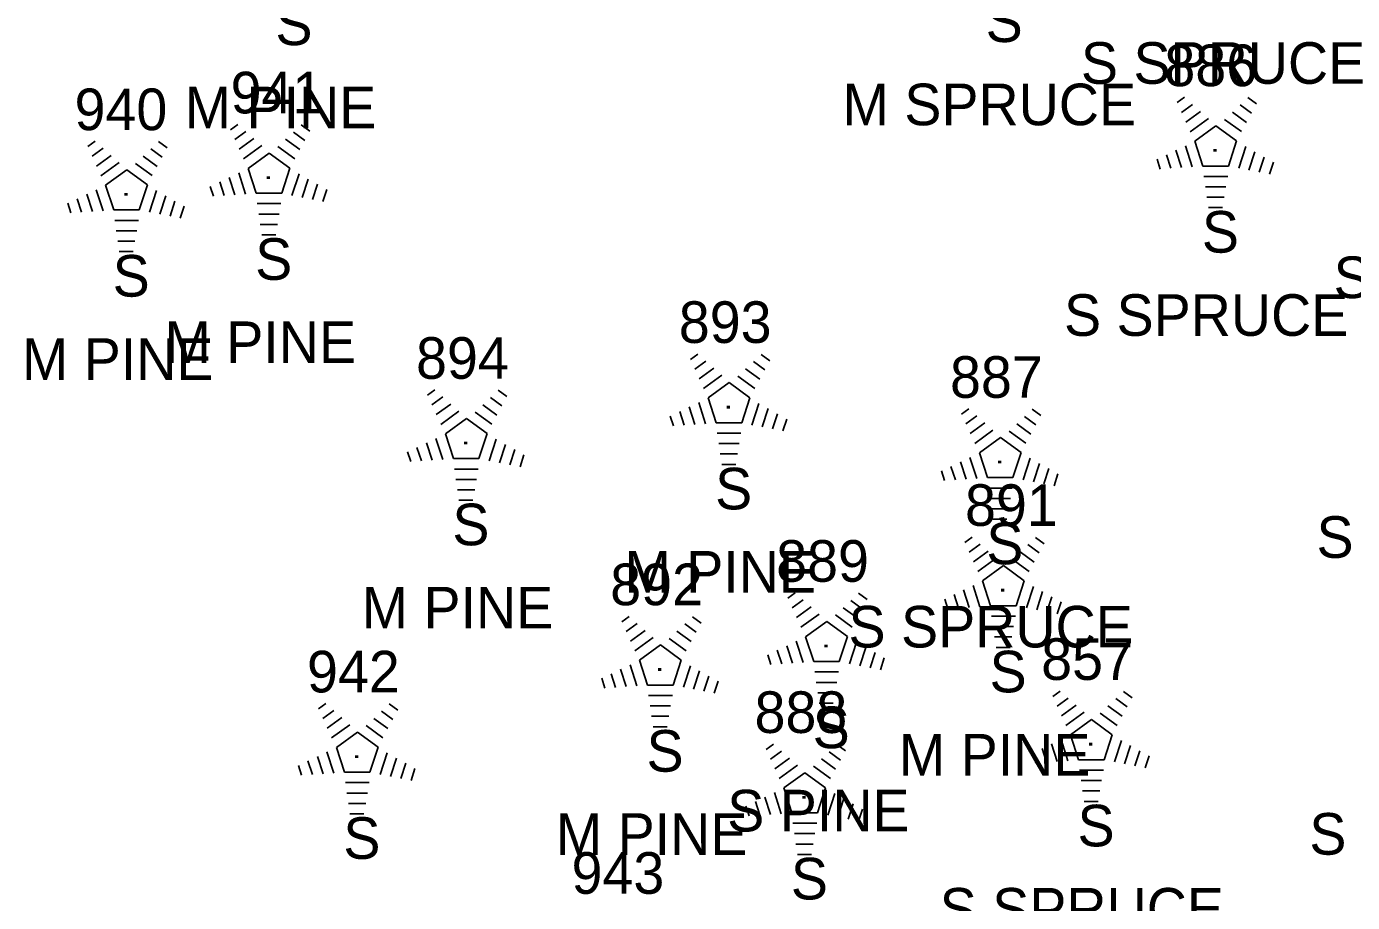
# Model space of a CAD drawing. Extents: x 1545627 to 1546562, y 571176 to 576667.
# Drawn here: x 1546147.4 to 1546211.1, y 572351.6 to 572393.7 of the extents above; entities that cross this region are included whole.
import ezdxf

# ---------------------------------------------------------------- set-up
doc = ezdxf.new("R2010")
doc.units = 0
for name, color, linetype in [('L_A', 7, 'Continuous'), ('L_C', 7, 'Continuous'), ('L_I', 7, 'Continuous'), ('LTC', 7, 'Continuous')]:
    doc.layers.add(name, color=color, linetype=linetype)

msp = doc.modelspace()

# ---------------------------------------------------------------- linework, layer by layer
at = {"layer": 'LTC'}
for p, q in [((1546202.707, 572390.014), (1546203.061, 572390.271)), ((1546206.105, 572390.254), (1546206.524, 572389.95)), ((1546202.916, 572389.548), (1546203.445, 572389.933)), ((1546203.126, 572389.083), (1546203.83, 572389.594)), ((1546205.363, 572389.558), (1546206.042, 572389.064)), ((1546205.734, 572389.906), (1546206.283, 572389.507)), ((1546157.171, 572388.707), (1546157.526, 572388.965)), ((1546160.57, 572388.948), (1546160.989, 572388.643)), ((1546203.335, 572388.617), (1546204.214, 572389.255)), ((1546203.56, 572388.162), (1546204.572, 572388.896)), ((1546204.572, 572388.896), (1546205.569, 572388.171)), ((1546204.992, 572389.209), (1546205.801, 572388.62)), ((1546150.316, 572387.9), (1546150.67, 572388.158)), ((1546153.714, 572388.141), (1546154.133, 572387.836)), ((1546157.381, 572388.242), (1546157.91, 572388.626)), ((1546157.59, 572387.776), (1546158.294, 572388.287)), ((1546159.827, 572388.251), (1546160.507, 572387.757)), ((1546160.198, 572388.6), (1546160.748, 572388.2)), ((1546203.56, 572388.162), (1546203.947, 572386.968)), ((1546205.569, 572388.171), (1546205.178, 572386.968)), ((1546150.525, 572387.435), (1546151.055, 572387.819)), ((1546150.735, 572386.969), (1546151.439, 572387.48)), ((1546153.343, 572387.792), (1546153.893, 572387.393)), ((1546157.8, 572387.31), (1546158.678, 572387.948)), ((1546158.025, 572386.855), (1546159.036, 572387.59)), ((1546159.036, 572387.59), (1546160.033, 572386.865)), ((1546159.456, 572387.903), (1546160.266, 572387.314)), ((1546202.195, 572387.51), (1546202.406, 572386.858)), ((1546202.65, 572387.726), (1546202.921, 572386.891)), ((1546203.105, 572387.943), (1546203.436, 572386.923)), ((1546206.006, 572387.9), (1546205.668, 572386.861)), ((1546206.451, 572387.65), (1546206.163, 572386.765)), ((1546150.945, 572386.503), (1546151.823, 572387.141)), ((1546152.601, 572387.096), (1546153.41, 572386.507)), ((1546152.972, 572387.444), (1546153.651, 572386.95)), ((1546158.025, 572386.855), (1546158.412, 572385.662)), ((1546160.033, 572386.865), (1546159.642, 572385.662)), ((1546201.739, 572387.293), (1546201.891, 572386.825)), ((1546205.178, 572386.968), (1546203.947, 572386.968)), ((1546206.895, 572387.4), (1546206.658, 572386.67)), ((1546207.34, 572387.15), (1546207.153, 572386.575)), ((1546151.169, 572386.048), (1546152.181, 572386.783)), ((1546152.181, 572386.783), (1546153.178, 572386.058)), ((1546156.659, 572386.203), (1546156.871, 572385.552)), ((1546157.115, 572386.42), (1546157.386, 572385.585)), ((1546157.57, 572386.636), (1546157.901, 572385.617)), ((1546160.471, 572386.594), (1546160.133, 572385.555)), ((1546160.915, 572386.344), (1546160.628, 572385.459)), ((1546205.139, 572386.468), (1546203.995, 572386.468)), ((1546150.259, 572385.613), (1546150.53, 572384.777)), ((1546150.715, 572385.829), (1546151.045, 572384.81)), ((1546151.169, 572386.048), (1546151.556, 572384.855)), ((1546153.178, 572386.058), (1546152.787, 572384.855)), ((1546153.615, 572385.787), (1546153.278, 572384.747)), ((1546156.204, 572385.987), (1546156.356, 572385.519)), ((1546159.642, 572385.662), (1546158.412, 572385.662)), ((1546161.36, 572386.094), (1546161.123, 572385.364)), ((1546161.804, 572385.843), (1546161.617, 572385.269)), ((1546205.055, 572385.968), (1546204.067, 572385.968)), ((1546149.348, 572385.179), (1546149.5, 572384.711)), ((1546149.804, 572385.396), (1546150.015, 572384.744)), ((1546154.06, 572385.536), (1546153.773, 572384.652)), ((1546154.505, 572385.286), (1546154.268, 572384.557)), ((1546154.949, 572385.036), (1546154.762, 572384.462)), ((1546159.604, 572385.162), (1546158.459, 572385.162)), ((1546204.972, 572385.468), (1546204.14, 572385.468)), ((1546204.888, 572384.968), (1546204.213, 572384.968)), ((1546152.787, 572384.855), (1546151.556, 572384.855)), ((1546152.748, 572384.355), (1546151.604, 572384.355)), ((1546159.52, 572384.662), (1546158.532, 572384.662)), ((1546152.665, 572383.855), (1546151.676, 572383.855)), ((1546159.436, 572384.162), (1546158.605, 572384.162)), ((1546159.352, 572383.662), (1546158.677, 572383.662)), ((1546152.581, 572383.355), (1546151.749, 572383.355)), ((1546152.497, 572382.855), (1546151.822, 572382.855)), ((1546179.296, 572377.674), (1546179.65, 572377.932)), ((1546182.694, 572377.914), (1546183.113, 572377.61)), ((1546179.505, 572377.209), (1546180.034, 572377.593)), ((1546182.323, 572377.566), (1546182.872, 572377.167)), ((1546179.715, 572376.743), (1546180.419, 572377.254)), ((1546179.924, 572376.277), (1546180.803, 572376.915)), ((1546181.581, 572376.869), (1546182.39, 572376.281)), ((1546181.952, 572377.218), (1546182.631, 572376.724)), ((1546166.656, 572375.95), (1546167.011, 572376.208)), ((1546170.054, 572376.191), (1546170.474, 572375.886)), ((1546180.149, 572375.822), (1546181.161, 572376.557)), ((1546181.161, 572376.557), (1546182.158, 572375.832)), ((1546166.866, 572375.485), (1546167.395, 572375.869)), ((1546167.075, 572375.019), (1546167.779, 572375.53)), ((1546169.312, 572375.494), (1546169.992, 572375)), ((1546169.683, 572375.842), (1546170.233, 572375.443)), ((1546179.239, 572375.387), (1546179.51, 572374.551)), ((1546179.694, 572375.603), (1546180.025, 572374.584)), ((1546180.149, 572375.822), (1546180.536, 572374.629)), ((1546182.158, 572375.832), (1546181.766, 572374.629)), ((1546182.595, 572375.561), (1546182.257, 572374.521)), ((1546167.285, 572374.553), (1546168.163, 572375.191)), ((1546167.509, 572374.098), (1546168.521, 572374.833)), ((1546168.521, 572374.833), (1546169.518, 572374.108)), ((1546168.941, 572375.146), (1546169.751, 572374.557)), ((1546178.328, 572374.953), (1546178.48, 572374.485)), ((1546178.784, 572375.17), (1546178.995, 572374.518)), ((1546183.04, 572375.31), (1546182.752, 572374.426)), ((1546183.484, 572375.06), (1546183.247, 572374.331)), ((1546183.929, 572374.81), (1546183.742, 572374.236)), ((1546192.34, 572375.038), (1546192.695, 572375.295)), ((1546192.55, 572374.572), (1546193.079, 572374.956)), ((1546195.367, 572374.93), (1546195.917, 572374.53)), ((1546195.739, 572375.278), (1546196.158, 572374.973)), ((1546167.509, 572374.098), (1546167.897, 572372.905)), ((1546169.518, 572374.108), (1546169.127, 572372.905)), ((1546181.766, 572374.629), (1546180.536, 572374.629)), ((1546181.728, 572374.129), (1546180.584, 572374.129)), ((1546192.76, 572374.106), (1546193.463, 572374.618)), ((1546192.969, 572373.64), (1546193.847, 572374.278)), ((1546194.625, 572374.233), (1546195.435, 572373.644)), ((1546194.997, 572374.581), (1546195.676, 572374.088)), ((1546166.144, 572373.446), (1546166.356, 572372.795)), ((1546166.599, 572373.663), (1546166.871, 572372.827)), ((1546167.055, 572373.879), (1546167.386, 572372.86)), ((1546169.956, 572373.837), (1546169.618, 572372.797)), ((1546170.4, 572373.587), (1546170.113, 572372.702)), ((1546181.644, 572373.629), (1546180.656, 572373.629)), ((1546193.194, 572373.185), (1546194.205, 572373.92)), ((1546194.205, 572373.92), (1546195.202, 572373.195)), ((1546165.689, 572373.23), (1546165.841, 572372.762)), ((1546169.127, 572372.905), (1546167.897, 572372.905)), ((1546170.845, 572373.337), (1546170.608, 572372.607)), ((1546171.289, 572373.086), (1546171.102, 572372.512)), ((1546181.561, 572373.129), (1546180.729, 572373.129)), ((1546192.739, 572372.966), (1546193.07, 572371.947)), ((1546193.194, 572373.185), (1546193.581, 572371.992)), ((1546195.202, 572373.195), (1546194.811, 572371.992)), ((1546195.64, 572372.924), (1546195.302, 572371.885)), ((1546169.089, 572372.405), (1546167.944, 572372.405)), ((1546181.477, 572372.629), (1546180.802, 572372.629)), ((1546191.373, 572372.317), (1546191.525, 572371.849)), ((1546191.828, 572372.533), (1546192.04, 572371.882)), ((1546192.284, 572372.75), (1546192.555, 572371.915)), ((1546196.085, 572372.674), (1546195.797, 572371.789)), ((1546196.529, 572372.424), (1546196.292, 572371.694)), ((1546196.973, 572372.173), (1546196.787, 572371.599)), ((1546169.005, 572371.905), (1546168.017, 572371.905)), ((1546194.811, 572371.992), (1546193.581, 572371.992)), ((1546168.921, 572371.405), (1546168.089, 572371.405)), ((1546168.837, 572370.905), (1546168.162, 572370.905)), ((1546194.773, 572371.492), (1546193.628, 572371.492)), ((1546194.689, 572370.992), (1546193.701, 572370.992)), ((1546194.605, 572370.492), (1546193.774, 572370.492)), ((1546194.522, 572369.992), (1546193.847, 572369.992)), ((1546192.494, 572368.88), (1546192.849, 572369.138)), ((1546195.892, 572369.12), (1546196.312, 572368.816)), ((1546192.704, 572368.415), (1546193.233, 572368.799)), ((1546192.913, 572367.949), (1546193.617, 572368.46)), ((1546195.15, 572368.424), (1546195.829, 572367.93)), ((1546195.521, 572368.772), (1546196.071, 572368.373)), ((1546193.123, 572367.483), (1546194.001, 572368.121)), ((1546193.347, 572367.028), (1546194.359, 572367.763)), ((1546194.359, 572367.763), (1546195.356, 572367.038)), ((1546194.779, 572368.075), (1546195.589, 572367.487)), ((1546183.987, 572366.196), (1546184.341, 572366.454)), ((1546187.385, 572366.437), (1546187.804, 572366.132)), ((1546192.437, 572366.593), (1546192.709, 572365.757)), ((1546192.893, 572366.809), (1546193.224, 572365.79)), ((1546193.347, 572367.028), (1546193.734, 572365.835)), ((1546195.356, 572367.038), (1546194.965, 572365.835)), ((1546195.794, 572366.767), (1546195.456, 572365.727)), ((1546196.238, 572366.516), (1546195.951, 572365.632)), ((1546184.196, 572365.731), (1546184.725, 572366.115)), ((1546187.014, 572366.088), (1546187.563, 572365.689)), ((1546191.527, 572366.159), (1546191.679, 572365.691)), ((1546191.982, 572366.376), (1546192.194, 572365.724)), ((1546194.965, 572365.835), (1546193.734, 572365.835)), ((1546196.683, 572366.266), (1546196.446, 572365.537)), ((1546197.127, 572366.016), (1546196.94, 572365.442)), ((1546175.995, 572365.069), (1546176.35, 572365.326)), ((1546179.393, 572365.309), (1546179.813, 572365.004)), ((1546184.406, 572365.265), (1546185.11, 572365.776)), ((1546184.615, 572364.799), (1546185.494, 572365.437)), ((1546186.272, 572365.392), (1546187.081, 572364.803)), ((1546186.643, 572365.74), (1546187.322, 572365.246)), ((1546194.927, 572365.335), (1546193.782, 572365.335)), ((1546176.205, 572364.603), (1546176.734, 572364.987)), ((1546176.414, 572364.137), (1546177.118, 572364.649)), ((1546178.651, 572364.612), (1546179.331, 572364.119)), ((1546179.022, 572364.961), (1546179.572, 572364.562)), ((1546184.84, 572364.344), (1546185.852, 572365.079)), ((1546185.852, 572365.079), (1546186.849, 572364.354)), ((1546194.843, 572364.835), (1546193.854, 572364.835)), ((1546176.624, 572363.672), (1546177.502, 572364.309)), ((1546176.848, 572363.217), (1546177.86, 572363.951)), ((1546177.86, 572363.951), (1546178.857, 572363.226)), ((1546178.28, 572364.264), (1546179.09, 572363.675)), ((1546183.93, 572363.909), (1546184.201, 572363.073)), ((1546184.385, 572364.125), (1546184.716, 572363.106)), ((1546184.84, 572364.344), (1546185.227, 572363.151)), ((1546186.849, 572364.354), (1546186.458, 572363.151)), ((1546187.286, 572364.083), (1546186.948, 572363.043)), ((1546194.759, 572364.335), (1546193.927, 572364.335)), ((1546183.019, 572363.476), (1546183.171, 572363.008)), ((1546183.475, 572363.692), (1546183.686, 572363.041)), ((1546187.731, 572363.833), (1546187.443, 572362.948)), ((1546188.175, 572363.583), (1546187.938, 572362.853)), ((1546188.62, 572363.332), (1546188.433, 572362.758)), ((1546194.675, 572363.835), (1546194, 572363.835)), ((1546175.938, 572362.781), (1546176.21, 572361.946)), ((1546176.394, 572362.997), (1546176.725, 572361.978)), ((1546176.848, 572363.217), (1546177.236, 572362.023)), ((1546178.857, 572363.226), (1546178.466, 572362.023)), ((1546179.295, 572362.955), (1546178.957, 572361.916)), ((1546179.739, 572362.705), (1546179.452, 572361.82)), ((1546186.458, 572363.151), (1546185.227, 572363.151)), ((1546186.419, 572362.651), (1546185.275, 572362.651)), ((1546175.028, 572362.348), (1546175.18, 572361.88)), ((1546175.483, 572362.564), (1546175.695, 572361.913)), ((1546178.466, 572362.023), (1546177.236, 572362.023)), ((1546180.184, 572362.455), (1546179.947, 572361.725)), ((1546180.628, 572362.204), (1546180.441, 572361.63)), ((1546186.335, 572362.151), (1546185.347, 572362.151)), ((1546178.428, 572361.523), (1546177.283, 572361.523)), ((1546186.252, 572361.651), (1546185.42, 572361.651)), ((1546196.725, 572361.478), (1546197.08, 572361.736)), ((1546196.935, 572361.013), (1546197.464, 572361.397)), ((1546199.752, 572361.371), (1546200.302, 572360.971)), ((1546200.124, 572361.719), (1546200.543, 572361.414)), ((1546161.413, 572360.878), (1546161.767, 572361.136)), ((1546161.622, 572360.413), (1546162.151, 572360.797)), ((1546164.44, 572360.77), (1546164.989, 572360.371)), ((1546164.811, 572361.119), (1546165.23, 572360.814)), ((1546178.344, 572361.023), (1546177.356, 572361.023)), ((1546186.168, 572361.151), (1546185.493, 572361.151)), ((1546197.144, 572360.547), (1546197.848, 572361.058)), ((1546197.354, 572360.081), (1546198.232, 572360.719)), ((1546199.381, 572361.022), (1546200.061, 572360.528)), ((1546161.832, 572359.947), (1546162.536, 572360.458)), ((1546162.041, 572359.481), (1546162.92, 572360.119)), ((1546163.698, 572360.074), (1546164.507, 572359.485)), ((1546164.069, 572360.422), (1546164.748, 572359.928)), ((1546178.26, 572360.523), (1546177.428, 572360.523)), ((1546197.579, 572359.626), (1546198.59, 572360.361)), ((1546198.59, 572360.361), (1546199.587, 572359.636)), ((1546199.01, 572360.674), (1546199.82, 572360.085)), ((1546162.266, 572359.026), (1546163.278, 572359.761)), ((1546163.278, 572359.761), (1546164.275, 572359.036)), ((1546178.176, 572360.023), (1546177.501, 572360.023)), ((1546197.579, 572359.626), (1546197.966, 572358.433)), ((1546199.587, 572359.636), (1546199.196, 572358.433)), ((1546161.811, 572358.807), (1546162.142, 572357.788)), ((1546162.266, 572359.026), (1546162.653, 572357.833)), ((1546164.275, 572359.036), (1546163.883, 572357.833)), ((1546182.937, 572358.928), (1546183.292, 572359.185)), ((1546183.147, 572358.462), (1546183.676, 572358.847)), ((1546185.965, 572358.82), (1546186.514, 572358.421)), ((1546186.336, 572359.168), (1546186.755, 572358.864)), ((1546196.213, 572358.974), (1546196.425, 572358.323)), ((1546196.669, 572359.191), (1546196.94, 572358.356)), ((1546197.124, 572359.407), (1546197.455, 572358.388)), ((1546200.025, 572359.365), (1546199.687, 572358.326)), ((1546200.469, 572359.115), (1546200.182, 572358.23)), ((1546200.914, 572358.865), (1546200.677, 572358.135)), ((1546160.445, 572358.157), (1546160.597, 572357.69)), ((1546160.901, 572358.374), (1546161.112, 572357.722)), ((1546161.356, 572358.591), (1546161.627, 572357.755)), ((1546164.712, 572358.765), (1546164.374, 572357.725)), ((1546165.157, 572358.515), (1546164.869, 572357.63)), ((1546165.601, 572358.265), (1546165.364, 572357.535)), ((1546183.357, 572357.997), (1546184.06, 572358.508)), ((1546183.566, 572357.531), (1546184.445, 572358.169)), ((1546185.594, 572358.472), (1546186.273, 572357.978)), ((1546195.758, 572358.758), (1546195.91, 572358.29)), ((1546199.196, 572358.433), (1546197.966, 572358.433)), ((1546201.358, 572358.614), (1546201.171, 572358.04)), ((1546163.883, 572357.833), (1546162.653, 572357.833)), ((1546166.046, 572358.014), (1546165.859, 572357.44)), ((1546183.791, 572357.076), (1546184.802, 572357.81)), ((1546184.802, 572357.81), (1546185.8, 572357.085)), ((1546185.222, 572358.123), (1546186.032, 572357.534)), ((1546199.158, 572357.933), (1546198.013, 572357.933)), ((1546163.845, 572357.333), (1546162.701, 572357.333)), ((1546183.791, 572357.076), (1546184.178, 572355.882)), ((1546185.8, 572357.085), (1546185.408, 572355.882)), ((1546199.074, 572357.433), (1546198.086, 572357.433)), ((1546198.99, 572356.933), (1546198.159, 572356.933)), ((1546163.761, 572356.833), (1546162.773, 572356.833)), ((1546163.678, 572356.333), (1546162.846, 572356.333)), ((1546182.425, 572356.424), (1546182.637, 572355.772)), ((1546182.881, 572356.64), (1546183.152, 572355.805)), ((1546183.336, 572356.857), (1546183.667, 572355.837)), ((1546186.237, 572356.814), (1546185.899, 572355.775)), ((1546186.682, 572356.564), (1546186.394, 572355.679)), ((1546187.126, 572356.314), (1546186.889, 572355.584)), ((1546198.906, 572356.433), (1546198.231, 572356.433)), ((1546163.594, 572355.833), (1546162.919, 572355.833)), ((1546181.97, 572356.207), (1546182.122, 572355.739)), ((1546185.408, 572355.882), (1546184.178, 572355.882)), ((1546187.57, 572356.064), (1546187.384, 572355.489)), ((1546185.37, 572355.382), (1546184.225, 572355.382)), ((1546185.286, 572354.882), (1546184.298, 572354.882)), ((1546185.202, 572354.382), (1546184.371, 572354.382)), ((1546185.119, 572353.882), (1546184.444, 572353.882))]:
    msp.add_line(p, q, dxfattribs=at)

# ---------------------------------------------------------------- texts
at = {"layer": 'L_A'}
for p in [(1546159.336, 572392.779), (1546193.497, 572392.928), (1546203.897, 572382.806), (1546158.362, 572381.499), (1546151.507, 572380.692), (1546180.486, 572370.466), (1546167.847, 572368.742), (1546193.531, 572367.829), (1546193.685, 572361.672), (1546185.177, 572358.988), (1546177.186, 572357.86), (1546197.916, 572354.27), (1546162.603, 572353.67), (1546184.128, 572351.72)]:
    msp.add_text('S', height=2, dxfattribs=at).set_placement(p)
at = {"layer": 'L_C'}
for s, p in [('S SPRUCE', (1546198.08, 572390.92)), ('M PINE', (1546154.974, 572388.779)), ('M SPRUCE', (1546186.615, 572388.928)), ('S SPRUCE', (1546210.234, 572380.621)), ('S SPRUCE', (1546197.267, 572378.806)), ('M PINE', (1546154, 572377.499)), ('M PINE', (1546147.144, 572376.692)), ('S SPRUCE', (1546209.411, 572368.137)), ('M PINE', (1546176.124, 572366.466)), ('M PINE', (1546163.485, 572364.742)), ('S SPRUCE', (1546186.901, 572363.829)), ('M PINE', (1546189.323, 572357.672)), ('S PINE', (1546181.067, 572354.988)), ('M PINE', (1546172.824, 572353.86)), ('S SPRUCE', (1546209.066, 572353.872)), ('S SPRUCE', (1546191.286, 572350.27))]:
    msp.add_text(s, height=2, dxfattribs=at).set_placement(p)
at = {"layer": 'L_I'}
for s, p in [('886', (1546202.094, 572390.806)), ('941', (1546157.181, 572389.499)), ('940', (1546149.672, 572388.692)), ('893', (1546178.738, 572378.466)), ('894', (1546166.099, 572376.742)), ('887', (1546191.783, 572375.829)), ('891', (1546192.504, 572369.672)), ('889', (1546183.421, 572366.988)), ('892', (1546175.438, 572365.86)), ('857', (1546196.168, 572362.27)), ('942', (1546160.855, 572361.67)), ('888', (1546182.38, 572359.72)), ('943', (1546173.578, 572351.992))]:
    msp.add_text(s, height=2, dxfattribs=at).set_placement(p)
at = {"layer": 'LTC'}
for p in [(1546204.454, 572387.91), (1546158.919, 572386.603), (1546152.063, 572385.796), (1546181.043, 572375.57), (1546168.404, 572373.846), (1546194.088, 572372.933), (1546194.242, 572366.776), (1546185.734, 572364.092), (1546177.743, 572362.964), (1546198.473, 572359.374), (1546163.16, 572358.774), (1546184.685, 572356.824)]:
    msp.add_text('.', height=1.037, rotation=270, dxfattribs=at).set_placement(p)

doc.saveas('drawing.dxf')
